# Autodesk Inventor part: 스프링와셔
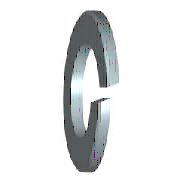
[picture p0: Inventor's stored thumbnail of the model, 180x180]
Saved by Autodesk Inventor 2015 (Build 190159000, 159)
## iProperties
IsCustomPart: 1
Created: 2012-02
Part Number: 스프링와셔
Material: 강철, 연강
Description: 스프링 와셔
Document SubType Name: Modeling
Standard: JIS B 1251
Designer: mduedu
Standards Organization: JIS
Language: ko-KR
Size Designation: 번호 2 4
Categories: <MemberInstance><Categories><Category DisplayName="조임쇠" InternalName="e4da775c-781d-43d5-af7c-5136215cf5a6" Mnemonic="FSTN"><Category DisplayName="와셔" InternalN
Density: 1 g/cm^3
Appearance: 파란색 - 벽 페인트 - 광택
Author: mduedu
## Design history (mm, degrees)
sketch "스케치1"
  geometry: C1 r 3.8 at (0, 0); C2 r 2.05 at (0, 0); 1 further point
  constraints: 2 centre point, 2 coincident
  dimensions: "d0" = 4.1 diameter of C2 (= SD1); "d1" = 7.6 diameter of C1 (= SD2)
extrude "본체" new body sketch "스케치1" distance "d2" = 1 (= SD); taper "d3" = 0 deg
sketch "스케치2"
  geometry: L1 (0, -2.05)-(0, 2.05) reference; L2 (1, 3.8)-(1, -3.8) reference; L3 (-1.2, 0)-(7.2, 0) reference; L4 (0, -0.2)-(1, 0.164); L5 (0, 0.2)-(1, 0.564)
  constraints: 4 end point, 4 point on line, 1 parallel
  dimensions: "d4" = 0.2 distance from line of L3 L4.start (= 0.2 x SD); "d5" = 0.2 distance from line of L3 L5.start (= 0.2 x SD); "d6" = 70 deg angle of L2 L4 (= FAWI)
extrude "절단부" cut sketch "스케치2" stored distance "d7" = 1 (= SD); taper "d8" = 0 deg
workaxis "Work Axis1"
workplane "Work Plane1"
body "Solid1"
other parameters: "SD1" = 4.1 [user parameter; used in 1 equation term], "SD2" = 7.6 [user parameter; used in 1 equation term], "SD" = 1 [user parameter; used in 4 equation terms], "FAWI" = 70 deg [user parameter; used in 1 equation term], "d9" = 0, "d10" = 0, "d11" = 0, "d12" = 0, "SDI" = 1.4 [user parameter], "NND" = 4 [user parameter]
